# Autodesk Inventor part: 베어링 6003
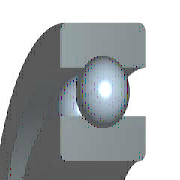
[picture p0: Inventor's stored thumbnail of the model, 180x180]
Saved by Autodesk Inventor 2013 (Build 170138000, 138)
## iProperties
IsCustomPart: 1
Created: 2009-02
Part Number: 베어링 6003
Material: 강, 연강
Description: 깊은 그루브 볼 베어링
Document SubType Name: Modeling
Standard: KS B 2023
Designer: 한국산업디자인학원
Standards Organization: KS
Language: ko-KR
Size Designation: 6003 - 17 x 35 x 10
Categories: <MemberInstance><Categories><Category DisplayName="샤프트 부품" InternalName="7f7aeb1f-a693-4053-b835-cee3144e0d98" Mnemonic="SHFT"><Category DisplayName="베어링" Inter
Density: 1 g/cm^3
Author: 한국산업디자인학원
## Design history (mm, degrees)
sketch "스케치" dims "d0" = 4.68 (= -0.26 x WD + 0.26 x BD)
  geometry: L1 (2.66, 13)-(7.34, 13); L2 (5, 13)-(5, 10.66); L3 (5, 13)-(5, 15.34); L4 (3.261, 11.434)-(0, 11.434); L5 (0, 8.5)-(10, 8.5); L6 (3.261, 14.566)-(0, 14.566); L7 (0, 17.5)-(10, 17.5); L8 (10, 8.5)-(10, 11.434); L9 (6.739, 11.434)-(10, 11.434); L10 (6.739, 14.566)-(10, 14.566); L11 (10, 17.5)-(10, 14.566); L12 (-1.4, 0)-(8.4, 0) reference; L13 (0, -0.3)-(0, 5.3) reference
  constraints: 22 end point, 4 point on line, 2 collinear, 2 perpendicular, 2 symmetric about line, 1 midpoint, 1 parallel, 14 other
  dimensions: "d9" = 17 diameter of L5 L12 (= WD); "d11" = 35 diameter of L7 L12 (= BD); "d12" = 10 distance between parallel lines of L8 L13 (= KB); "d13" = 22.868 diameter of L9 L12 (= 0.326 x BD + 0.674 x WD)
revolve "본체" stored, may be unused: angle "d6" = 90 deg
revolve "볼" stored, may be unused: angle "d7" = 90 deg
pattern_circular "IDS_ARRAYBALL[SIMPL:T]" dims angle "d3" = 360 deg
body "Solid1"
fillet "모깎기1" dims "d1" = 0.3 (= KRS)
other parameters: "WD" = 17 [user parameter; used in 5 equation terms], "BD" = 35 [user parameter; used in 5 equation terms], "KB" = 10 [user parameter; used in 1 equation term], "KRS" = 0.3 [user parameter; used in 1 equation term], "d4" = 0, "d5" = 0, "d8" = 0, "d14" = 0, "d15" = 0, "BBA" = 0 [user parameter], "BC0" = 3250000 [user parameter], "BC" = 6050000 [user parameter], "BR" = 17.5 (= 0.5 x BD) [user parameter], "WR" = 8.5 (= 0.5 x WD) [user parameter]
